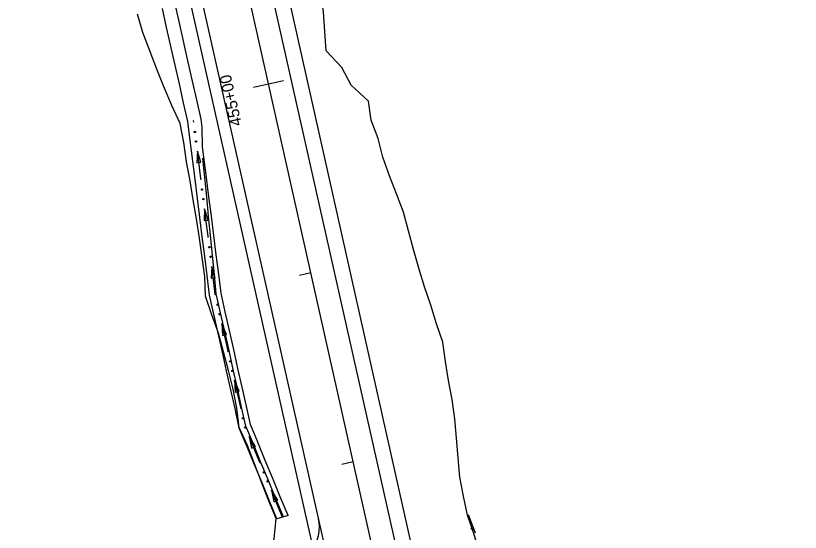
# Model space of a CAD drawing. Extents: x 948761 to 996004, y 1858548 to 1925175.
# Drawn here: x 957814.6 to 958220.1, y 1919035.8 to 1919302.7 of the extents above; entities that cross this region are included whole.
import ezdxf

# ---------------------------------------------------------------- set-up
doc = ezdxf.new("R2010")
doc.units = 0
for name, color, linetype in [('62', 7, 'Continuous'), ('R_Horz Alg', 7, 'Continuous'), ('R_Horz Alg Annot', 7, 'Continuous'), ('R_Proposed Const Limits', 7, 'Continuous'), ('R_Proposed Road', 7, 'Continuous')]:
    doc.layers.add(name, color=color, linetype=linetype)

msp = doc.modelspace()

# ---------------------------------------------------------------- linework, layer by layer
at = {"layer": '62'}
for p, q in [((957908.48, 1919232.8), (957908.18, 1919226.71)), ((957910.28, 1919226.98), (957908.48, 1919232.8)), ((957908.18, 1919226.71), (957910.28, 1919226.98)), ((957912.24, 1919203), (957911.94, 1919196.91)), ((957914.04, 1919197.18), (957912.24, 1919203)), ((957911.94, 1919196.91), (957914.04, 1919197.18)), ((957915.98, 1919173.19), (957915.67, 1919167.11)), ((957917.77, 1919167.37), (957915.98, 1919173.19)), ((957915.67, 1919167.11), (957917.77, 1919167.37)), ((957921.2, 1919143.65), (957921.49, 1919137.56)), ((957923.55, 1919138.03), (957921.2, 1919143.65)), ((957921.49, 1919137.56), (957923.55, 1919138.03)), ((957927.76, 1919114.34), (957928.04, 1919108.25)), ((957930.1, 1919108.71), (957927.76, 1919114.34)), ((957928.04, 1919108.25), (957930.1, 1919108.71)), ((957935.23, 1919085.31), (957936.55, 1919079.37)), ((957938.51, 1919080.18), (957935.23, 1919085.31)), ((957936.55, 1919079.37), (957938.51, 1919080.18)), ((957946.72, 1919057.56), (957948.04, 1919051.61)), ((957950, 1919052.42), (957946.72, 1919057.56)), ((957948.04, 1919051.61), (957950, 1919052.42)), ((957955.36, 1919044.5), (957949.56, 1919042.83))]:
    msp.add_line(p, q, dxfattribs=at)
for points in [[(957949.56, 1919042.83), (957945.81, 1919051.93), (957941.92, 1919061.3), (957938.05, 1919070.68), (957934.16, 1919080.06), (957930.18, 1919089.68), (957927.96, 1919099.7), (957925.78, 1919109.45), (957923.6, 1919119.21), (957921.42, 1919128.97), (957919.23, 1919138.73), (957917.04, 1919148.48), (957914.81, 1919158.38), (957913.54, 1919168.49), (957912.3, 1919178.46), (957911.05, 1919188.43), (957909.8, 1919198.4), (957908.54, 1919208.36), (957907.29, 1919218.33), (957904.76, 1919238.26), (957903.51, 1919248.08), (957901.36, 1919257.7), (957899.17, 1919267.46), (957896.98, 1919277.22), (957892.6, 1919296.73), (957890.41, 1919306.49)], [(957911.22, 1919235), (957910.94, 1919245.19), (957910.42, 1919249.29), (957908.19, 1919259.23), (957906, 1919268.99), (957903.81, 1919278.75), (957899.43, 1919298.26), (957897.24, 1919308.02)], [(957906.58, 1919247.72), (957906.47, 1919248.6)], [(957906.59, 1919247.68), (957906.58, 1919247.72)], [(957910.37, 1919217.92), (957910.27, 1919218.71), (957909, 1919228.67), (957908.48, 1919232.8)], [(957955.36, 1919044.5), (957951.35, 1919054.22), (957947.47, 1919063.6), (957943.59, 1919072.98), (957939.71, 1919082.36), (957935.92, 1919091.49), (957933.81, 1919101), (957931.64, 1919110.76), (957929.45, 1919120.52), (957927.28, 1919130.28), (957925.09, 1919140.04), (957922.9, 1919149.8), (957920.73, 1919159.41), (957919.5, 1919169.24), (957918.25, 1919179.21), (957917, 1919189.18), (957915.75, 1919199.14), (957914.5, 1919209.11), (957913.24, 1919219.08), (957911.22, 1919235)], [(957918.26, 1919159.01), (957917.27, 1919169.03), (957916.3, 1919179.06), (957915.31, 1919189.09), (957914.32, 1919199.12), (957913.33, 1919209.15), (957912.35, 1919219.17), (957911.35, 1919229.2)], [(957910.37, 1919217.88), (957910.37, 1919217.92)], [(957914.11, 1919188.11), (957914.02, 1919188.8), (957912.77, 1919198.77), (957912.24, 1919203)], [(957914.11, 1919188.08), (957914.11, 1919188.11)], [(957917.9, 1919158.32), (957917.77, 1919158.9), (957916.52, 1919168.86), (957915.98, 1919173.19)], [(957917.91, 1919158.28), (957917.9, 1919158.32)], [(957952.93, 1919043.8), (957949.07, 1919053.18), (957945.18, 1919062.56), (957941.31, 1919071.94), (957937.42, 1919081.32), (957933.54, 1919090.69), (957931.37, 1919100.46), (957929.2, 1919110.22), (957927.01, 1919119.98), (957924.84, 1919129.74), (957922.65, 1919139.49), (957920.46, 1919149.25), (957918.26, 1919159.01)], [(957924.49, 1919129.01), (957924.35, 1919129.63), (957922.16, 1919139.39), (957921.2, 1919143.65)], [(957924.49, 1919128.98), (957924.49, 1919129.01)], [(957931.03, 1919099.7), (957930.88, 1919100.35), (957928.71, 1919110.11), (957927.76, 1919114.34)], [(957931.04, 1919099.66), (957931.03, 1919099.69)], [(957940.97, 1919071.46), (957940.82, 1919071.83), (957936.93, 1919081.21), (957935.23, 1919085.31)], [(957940.99, 1919071.42), (957940.97, 1919071.45)], [(957952.45, 1919043.69), (957948.58, 1919053.07), (957946.72, 1919057.56)], [(958075.03, 1918835.48), (958073.6, 1918845.41), (958073.03, 1918849.38), (958072.16, 1918855.34), (958070.73, 1918865.26), (958069.3, 1918875.19), (958067.99, 1918885.15), (958067.85, 1918895.36), (958067.71, 1918905.58), (958067.59, 1918915.8), (958067.5, 1918926.03), (958067.42, 1918936.26), (958067.33, 1918946.49), (958067.24, 1918956.72), (958067.15, 1918966.95), (958067.07, 1918977.18), (958066.99, 1918987.41), (958063.87, 1918996.96), (958060.75, 1919006.51), (958057.63, 1919016.06), (958054.52, 1919025.6), (958052.28, 1919032.28), (958051.32, 1919035.14), (958048.11, 1919044.66)], [(958048.89, 1919042.34), (958048.11, 1919044.66)], [(958048.9, 1919042.31), (958048.89, 1919042.34)]]:
    msp.add_lwpolyline(points, dxfattribs=at)
for centre in [(957907.18, 1919242.73), (957907.81, 1919237.76), (957910.96, 1919212.93), (957911.58, 1919207.96), (957914.7, 1919183.13), (957915.32, 1919178.16), (957918.97, 1919153.41), (957920.07, 1919148.53), (957925.54, 1919124.1), (957926.63, 1919119.21), (957932.08, 1919094.78), (957933.28, 1919089.92), (957942.86, 1919066.8), (957944.77, 1919062.17), (958050.46, 1919037.57)]:
    msp.add_circle(centre, 0.375, dxfattribs=at)
at = {"layer": 'R_Horz Alg'}
msp.add_line((958200.6, 1918129.72), (957843.86, 1919719.4), dxfattribs=at)
at = {"layer": 'R_Horz Alg Annot'}
for points in [[(957937.46, 1919265.8), (957953.07, 1919269.31)], [(957961.31, 1919168.67), (957967.16, 1919169.98)], [(957983.2, 1919071.09), (957989.06, 1919072.41)]]:
    msp.add_lwpolyline(points, dxfattribs=at)
at = {"layer": 'R_Proposed Const Limits'}
for points in [[(957975.14, 1919284.51), (957974.35, 1919294.58), (957973.71, 1919304.68), (957972.18, 1919314.59), (957970.47, 1919324.45), (957969.2, 1919330.27), (957983.43, 1919338.64)], [(957899.61, 1919247.06), (957895.33, 1919256.35), (957891.37, 1919265.71), (957887.51, 1919275.09), (957883.94, 1919284.54), (957880.39, 1919293.99), (957877.49, 1919303.59)], [(958048.11, 1919044.66), (958045.96, 1919054.43), (958044.11, 1919064.27), (958043.23, 1919074.31), (958042.39, 1919084.38), (958041.63, 1919094.45), (958040.21, 1919104.38), (958038.23, 1919114.19), (958036.81, 1919124.12), (958035.29, 1919134.03), (958032.17, 1919143.57), (958029.18, 1919153.15), (958025.93, 1919162.67), (958023.02, 1919172.27), (958020.15, 1919181.87), (958017.63, 1919191.55), (958015.04, 1919201.22), (958011.35, 1919210.64), (958007.74, 1919220.08), (958004.43, 1919229.59), (958002.02, 1919239.29), (957998.3, 1919248.71), (957996.88, 1919258.64), (957987.94, 1919266.88), (957983.08, 1919276.04), (957975.14, 1919284.51)], [(957949.21, 1919042.97), (957945.32, 1919052.34), (957941.66, 1919061.77), (957938.08, 1919071.22), (957934.34, 1919080.63), (957930.17, 1919089.94), (957928.86, 1919099.89), (957926.92, 1919109.71), (957924.61, 1919119.44), (957922.05, 1919129.11), (957919.43, 1919138.77), (957915.93, 1919148.24), (957912.71, 1919157.76), (957912.31, 1919167.92), (957910.93, 1919177.86), (957909.57, 1919187.8), (957908, 1919197.7), (957906.29, 1919207.56), (957904.77, 1919217.47), (957902.94, 1919227.31), (957901.41, 1919237.22), (957899.61, 1919247.06)], [(957925.38, 1919016.47), (957944.56, 1919020.11), (957944.25, 1919021.36), (957948.18, 1919032.49), (957949.21, 1919042.97)], [(958052.26, 1919035.35), (958048.68, 1919044.79)]]:
    msp.add_lwpolyline(points, dxfattribs=at)
at = {"layer": 'R_Proposed Road'}
for p, q in [((958220.12, 1918134.1), (957863.38, 1919723.78)), ((958212.31, 1918132.34), (957855.57, 1919722.03)), ((958034.23, 1918734.09), (957814.59, 1919712.84)), ((958040.09, 1918735.4), (957820.45, 1919714.15))]:
    msp.add_line(p, q, dxfattribs=at)
msp.add_arc((957951.59, 1919038.42), 20, 280.8892, 12.6481, dxfattribs=at)

# ---------------------------------------------------------------- texts
at = {"layer": 'R_Horz Alg Annot'}
msp.add_text('455+00', height=6, rotation=102.6481, dxfattribs=at).set_placement((957931.56, 1919246.4))

doc.saveas('drawing.dxf')
